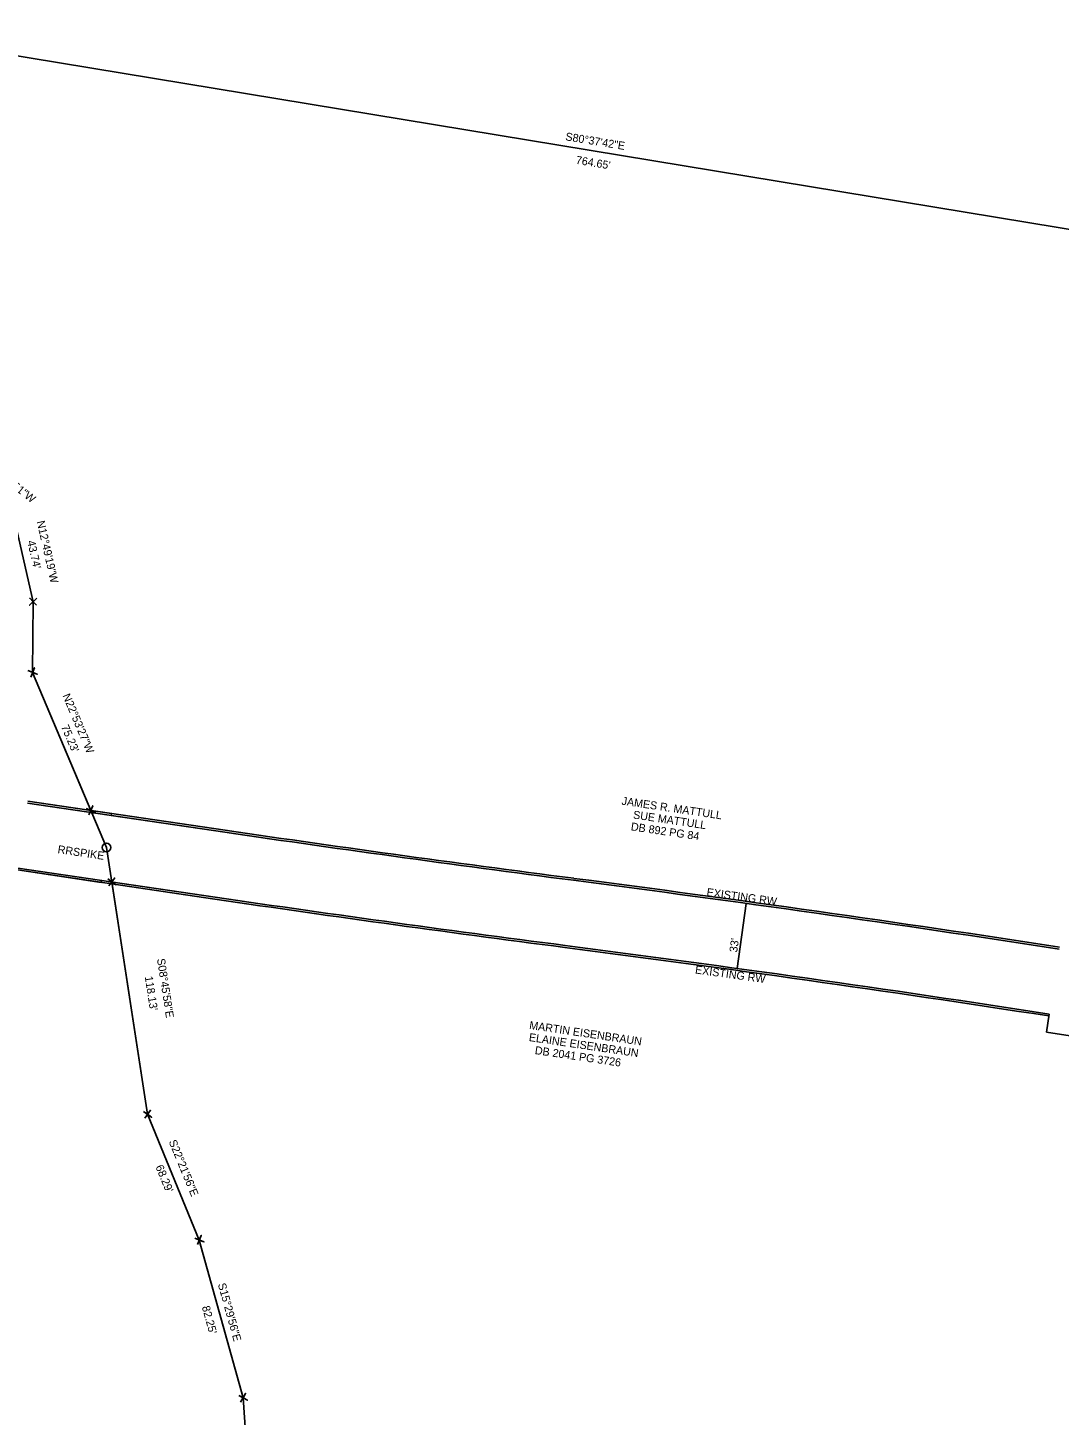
# Model space of a CAD drawing. Extents: x 1107874 to 1110849, y 645477 to 647181.
# Drawn here: x 1109050 to 1109568, y 646183 to 646880 of the extents above; entities that cross this region are included whole.
import ezdxf

# ---------------------------------------------------------------- set-up
doc = ezdxf.new("R2010")
doc.units = 0
for name, color, linetype in [('Exist Property Corner CELL', 7, 'Continuous'), ('Exist Property Iron Pin CELL', 7, 'Continuous'), ('Exist Property Line', 7, 'Continuous'), ('Exist Property Text', 7, 'Continuous'), ('Exist Right of Way Line', 7, 'Continuous'), ('Exist Right of Way Text', 7, 'Continuous')]:
    doc.layers.add(name, color=color, linetype=linetype)

msp = doc.modelspace()

# ---------------------------------------------------------------- linework, layer by layer
at = {"layer": 'Exist Property Corner CELL'}
for p, q in [((1109052.54, 646591.66), (1109052.54, 646591.66)), ((1109052.24, 646556.18), (1109052.24, 646556.18)), ((1109081.5, 646486.88), (1109081.5, 646486.88)), ((1109092.03, 646450.95), (1109092.03, 646450.95)), ((1109110.04, 646334.21), (1109110.04, 646334.21)), ((1109136.02, 646271.05), (1109136.02, 646271.05)), ((1109158, 646191.79), (1109158, 646191.79))]:
    msp.add_line(p, q, dxfattribs=at)
for points in [[(1109054.3, 646589.88), (1109050.79, 646593.45), (1109052.54, 646591.66), (1109050.76, 646589.91), (1109054.33, 646593.41)], [(1109049.93, 646557.13), (1109054.56, 646555.24), (1109052.24, 646556.18), (1109053.18, 646558.5), (1109051.3, 646553.87)], [(1109079.19, 646487.82), (1109083.82, 646485.94), (1109081.5, 646486.88), (1109082.45, 646489.19), (1109080.56, 646484.56)], [(1109090.02, 646452.43), (1109094.05, 646449.48), (1109092.03, 646450.95), (1109093.51, 646452.97), (1109090.56, 646448.94)], [(1109108.02, 646335.68), (1109112.05, 646332.73), (1109110.04, 646334.21), (1109111.51, 646336.22), (1109108.56, 646332.19)], [(1109133.71, 646272.02), (1109138.33, 646270.09), (1109136.02, 646271.05), (1109136.98, 646273.36), (1109135.06, 646268.75)], [(1109155.82, 646193.03), (1109160.18, 646190.56), (1109158, 646191.79), (1109159.23, 646193.97), (1109156.77, 646189.62)]]:
    msp.add_lwpolyline(points, dxfattribs=at)
at = {"layer": 'Exist Property Iron Pin CELL'}
for radius in [2.2, 0.0707]:
    msp.add_circle((1109089.36, 646468.26), radius, dxfattribs=at)
at = {"layer": 'Exist Property Line'}
for p, q in [((1108959.02, 646880.02), (1109713.46, 646755.51)), ((1109052.54, 646591.66), (1109042.84, 646634.31)), ((1109052.24, 646556.18), (1109052.54, 646591.66)), ((1109089.36, 646468.26), (1109052.24, 646556.18)), ((1109081.5, 646486.88), (1109052.24, 646556.18)), ((1109089.36, 646468.26), (1109110.04, 646334.21)), ((1109092.03, 646450.95), (1109110.04, 646334.21)), ((1109110.04, 646334.21), (1109136.02, 646271.05)), ((1109136.02, 646271.05), (1109158, 646191.79)), ((1109158, 646191.79), (1109162.44, 646126.61))]:
    msp.add_line(p, q, dxfattribs=at)
at = {"layer": 'Exist Right of Way Line'}
for p, q in [((1109049.68, 646490.57), (1109143.13, 646476.77)), ((1109049.82, 646491.56), (1109143.27, 646477.76)), ((1109049.82, 646491.56), (1109091.89, 646485.34)), ((1109091.89, 646485.34), (1109091.74, 646484.36)), ((1109091.74, 646484.36), (1109143.13, 646476.77)), ((1109044.71, 646456.93), (1109138.16, 646443.13)), ((1109044.71, 646456.93), (1109086.77, 646450.72)), ((1109044.86, 646457.92), (1109138.31, 646444.12)), ((1109086.77, 646450.72), (1109086.92, 646451.71)), ((1109086.92, 646451.71), (1109138.31, 646444.12)), ((1109561.58, 646375.47), (1109562.98, 646384.59))]:
    msp.add_line(p, q, dxfattribs=at)
msp.add_lwpolyline([(1109561.58, 646375.47), (1109597.34, 646369.97)], dxfattribs=at)
for centre, radius, start, end in [((1110601.62, 656353.16), 9983.5, 261.599575, 262.647299), ((1110601.62, 656353.16), 9983.5, 261.599575, 262.647299), ((1110601.62, 656353.16), 9982.5, 261.599575, 262.647299), ((1108042.08, 636517.61), 10016.5, 81.23737, 82.647299), ((1108042.08, 636517.61), 10016.5, 81.23737, 82.647299), ((1108042.08, 636517.61), 10017.5, 81.23737, 82.647299), ((1110601.62, 656353.16), 10017.5, 261.599575, 262.647299), ((1110601.62, 656353.16), 10016.5, 261.599575, 262.647299), ((1110601.62, 656353.16), 10016.5, 261.599575, 262.647299), ((1108042.08, 636517.61), 9983.5, 81.23737, 82.647299), ((1108042.08, 636517.61), 9983.5, 81.23737, 82.647299), ((1108042.08, 636517.61), 9982.5, 81.23737, 82.647299)]:
    msp.add_arc(centre, radius, start, end, dxfattribs=at)
at = {"layer": 'Exist Right of Way Text'}
for p, q in [((1109406.16, 646407.49), (1109410.67, 646440.18)), ((1109410.67, 646440.18), (1109406.16, 646407.49))]:
    msp.add_line(p, q, dxfattribs=at)

# ---------------------------------------------------------------- texts
at = {"layer": 'Exist Property Text'}
for s, rotation, p in [('S80°37\'42"E', 350.62823, (1109319.71, 646823.53)), ("764.65'", 350.62823, (1109324.96, 646811.72)), ('N52°02\'51"W', 322.0474, (1109026.61, 646660.77)), ('N12°49\'19"W', 282.82184, (1109054.3, 646631.93)), ("43.74'", 282.82184, (1109049.52, 646622.01)), ('N22°53\'27"W', 292.8909, (1109067.19, 646544.54)), ("75.23'", 292.8909, (1109066.49, 646528.91)), ('JAMES R. MATTULL', 351.59957, (1109347.99, 646489.77)), ('SUE MATTULL', 351.59957, (1109353.72, 646482.83)), ('DB 892 PG 84', 351.59957, (1109352.61, 646476.9)), ('RRSPIKE', 351.59957, (1109064.64, 646465.45)), ('S08°45\'58"E', 278.76603, (1109114.72, 646412.23)), ("118.13'", 278.76603, (1109108.6, 646403.33)), ('MARTIN EISENBRAUN', 351.59957, (1109301.57, 646377.12)), ('ELAINE EISENBRAUN', 351.59957, (1109301.38, 646371.05)), ('DB 2041 PG 3726', 351.59957, (1109304.37, 646364.51)), ('S22°21\'56"E', 292.36548, (1109120.58, 646320.46)), ("68.29'", 292.36548, (1109113.92, 646307.84)), ('S15°29\'56"E', 285.49881, (1109145.29, 646248.85)), ("82.25'", 285.49881, (1109137.25, 646237.42))]:
    msp.add_text(s, height=4.02, rotation=rotation, dxfattribs=at).set_placement(p)
at = {"layer": 'Exist Right of Way Text'}
for s, rotation, p in [('EXISTING RW', 352.16016, (1109390.66, 646443.91)), ("33'", 82.14695, (1109406.2, 646415.37)), ('EXISTING RW', 352.1629, (1109384.9, 646404.99))]:
    msp.add_text(s, height=4.02, rotation=rotation, dxfattribs=at).set_placement(p)

doc.saveas('drawing.dxf')
